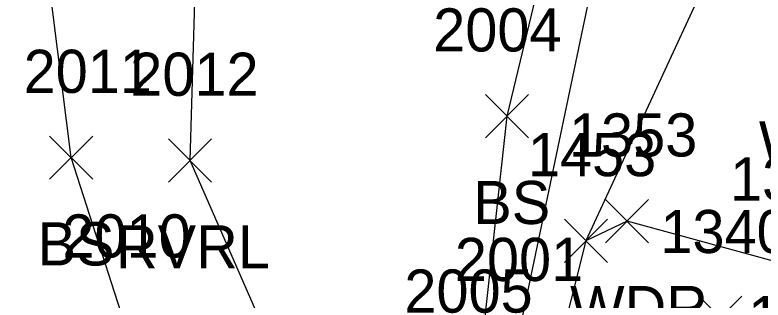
# Model space of a CAD drawing. Extents: x 1638344 to 1639591, y 610835 to 612202.
# Drawn here: x 1638706.21 to 1638740.88, y 611728.1 to 611741.32 of the extents above; entities that cross this region are included whole.
import ezdxf

# ---------------------------------------------------------------- set-up
doc = ezdxf.new("R2010")
doc.units = 0
for name, color, linetype in [('L_A', 7, 'Continuous'), ('L_I', 7, 'Continuous'), ('L_TIC', 7, 'Continuous'), ('LARO', 7, 'Continuous'), ('LAWA', 7, 'Continuous'), ('LAWE', 7, 'Continuous'), ('LELB', 7, 'Continuous')]:
    doc.layers.add(name, color=color, linetype=linetype)

msp = doc.modelspace()

# ---------------------------------------------------------------- linework, layer by layer
at = {"layer": 'L_TIC'}
for points in [[(1638728.011, 611735.626), (1638730.011, 611737.626)], [(1638730.011, 611735.626), (1638728.011, 611737.626)], [(1638707.812, 611733.706), (1638709.812, 611735.706)], [(1638709.812, 611733.706), (1638707.812, 611735.706)], [(1638713.323, 611733.571), (1638715.323, 611735.571)], [(1638715.323, 611733.571), (1638713.323, 611735.571)], [(1638733.58, 611730.756), (1638735.58, 611732.756)], [(1638735.58, 611730.756), (1638733.58, 611732.756)], [(1638731.677, 611729.845), (1638733.677, 611731.845)], [(1638733.677, 611729.845), (1638731.677, 611731.845)], [(1638731.677, 611729.845), (1638733.677, 611731.845)], [(1638733.677, 611729.845), (1638731.677, 611731.845)], [(1638737.904, 611726.28), (1638739.904, 611728.28)], [(1638739.904, 611726.28), (1638737.904, 611728.28)]]:
    msp.add_lwpolyline(points, dxfattribs=at)
at = {"layer": 'LARO'}
msp.add_lwpolyline([(1638729.448, 611725.986), (1638733.976, 611747.615), (1638731.968, 611748.953), (1638726.496, 611751.953), (1638720.235, 611753.465), (1638715.218, 611753.975), (1638712.56, 611755.84), (1638710.104, 611757.938), (1638706.667, 611763.644), (1638707.917, 611780.066), (1638708.84, 611791.218), (1638711.838, 611808.581), (1638711.099, 611825.207)], dxfattribs=at)
at = {"layer": 'LAWA'}
msp.add_lwpolyline([(1638745.509, 611792.396), (1638742.095, 611779.611), (1638747.744, 611767.046), (1638752.548, 611763.054), (1638747.527, 611752.68), (1638744.238, 611741.251), (1638742.049, 611729.716), (1638734.58, 611731.756), (1638732.677, 611730.845), (1638730.637, 611722.727)], dxfattribs=at)
at = {"layer": 'LAWE'}
msp.add_lwpolyline([(1638671.011, 611601.41), (1638687.934, 611612.159), (1638702.816, 611621.305), (1638722.828, 611637.898), (1638722.694, 611666.366), (1638723.119, 611679.868), (1638719.094, 611692.553), (1638717.187, 611697.341), (1638711.048, 611700.649), (1638718.685, 611716.114), (1638719.359, 611723.061), (1638714.323, 611734.571), (1638714.704, 611747.214), (1638712.56, 611755.84), (1638714.994, 611761.22), (1638711.865, 611767.72), (1638710.522, 611777.786), (1638714.936, 611789.326), (1638716.942, 611806.826), (1638715.698, 611824.36)], dxfattribs=at)
at = {"layer": 'LELB'}
for points in [[(1638739.639, 611795.779), (1638737.982, 611789.384), (1638728.755, 611782.451), (1638734.71, 611771.274), (1638743.68, 611760.781), (1638742.219, 611751.498), (1638732.677, 611730.845)], [(1638721.028, 611680.57), (1638715.476, 611695.81), (1638710.279, 611698.997), (1638709.836, 611702.955), (1638709.677, 611706.854), (1638712.785, 611716.361), (1638711.261, 611727.073), (1638708.812, 611734.706), (1638707.325, 611746.484), (1638710.104, 611757.938)], [(1638731.968, 611748.953), (1638729.011, 611736.626), (1638727.673, 611724.518)]]:
    msp.add_lwpolyline(points, dxfattribs=at)

# ---------------------------------------------------------------- texts
at = {"layer": 'L_A'}
for s, p in [('WALL', (1638740.693, 611734.391)), ('BS', (1638727.452, 611731.626)), ('BS', (1638707.253, 611729.706)), ('RVRL', (1638710.89, 611729.571)), ('WDR', (1638731.942, 611726.756))]:
    msp.add_text(s, height=2, dxfattribs=at).set_placement(p)
at = {"layer": 'L_I'}
for s, p in [('2004', (1638725.594, 611739.626)), ('2011', (1638706.607, 611737.706)), ('2012', (1638711.551, 611737.571)), ('1353', (1638731.887, 611734.756)), ('1453', (1638729.984, 611733.845)), ('1453', (1638729.984, 611733.845)), ('1352', (1638739.356, 611732.716)), ('1340', (1638736.124, 611730.28)), ('2010', (1638708.403, 611730.073)), ('2001', (1638726.598, 611728.986)), ('2001', (1638726.598, 611728.986)), ('2005', (1638724.256, 611727.518)), ('2005', (1638724.256, 611727.518)), ('1024', (1638740.199, 611726.288))]:
    msp.add_text(s, height=2, dxfattribs=at).set_placement(p)

doc.saveas('drawing.dxf')
